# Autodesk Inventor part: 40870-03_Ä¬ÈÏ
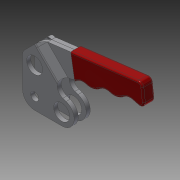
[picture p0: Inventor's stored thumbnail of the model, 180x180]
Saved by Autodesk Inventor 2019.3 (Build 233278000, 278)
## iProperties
Created: 2010-06
Part Number: 40870-03_Ä¬ÈÏ
Material: Ogólny
Document SubType Name: Modeling
Designer: CADENGINEERING4
Density: 1 g/cm^3
Appearance: Domyślna
Author: CADENGINEERING4
Revision Number: ÈÎºÎ
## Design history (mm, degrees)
feature "NONE"
feature "NONE:1"
feature "NONE:2"
feature "NONE:3"
feature "NONE:4"
node "Bryła1"
node "Bryła2"
node "Bryła3"
node "Bryła4"
node "Bryła5"
